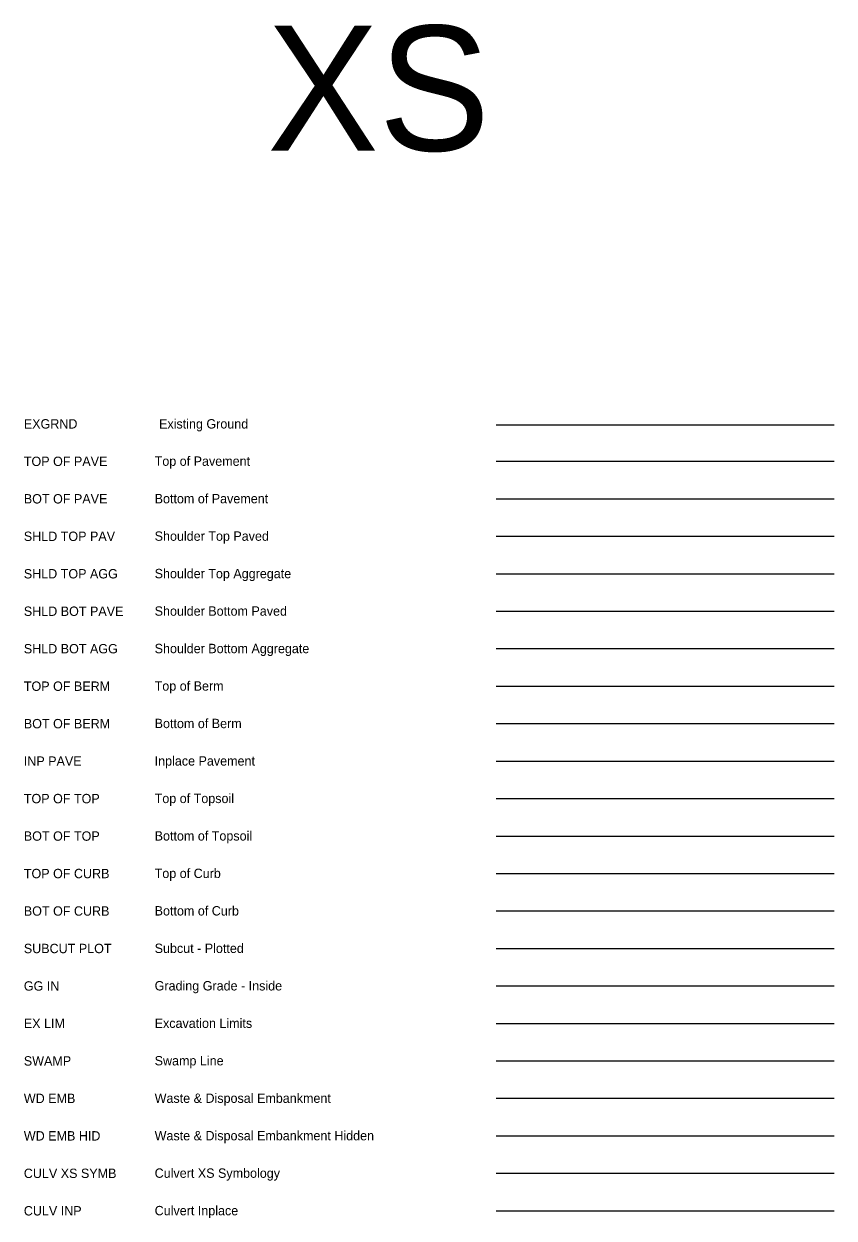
# Model space of a CAD drawing. Extents: x 2147716 to 2176321, y 2125040 to 2131750.
# Drawn here: x 2147716 to 2148364, y 2128683 to 2129640 of the extents above; entities that cross this region are included whole.
import ezdxf

# ---------------------------------------------------------------- set-up
doc = ezdxf.new("R2010")
doc.units = 0
for name, color, linetype in [('AGG HID', 7, 'Continuous'), ('BPFG CG BOT', 7, 'Continuous'), ('BPFG PAVE BOT', 7, 'Continuous'), ('BPFG SHLD BOT PAVE', 7, 'Continuous'), ('BPFG SWALK BOT', 7, 'Continuous'), ('CULV', 7, 'Continuous'), ('CULV INP', 7, 'Continuous'), ('DETAIL TXT', 7, 'Continuous'), ('EX LIM', 7, 'Continuous'), ('GRADE', 7, 'Continuous'), ('GRND INP', 7, 'Continuous'), ('PAVE INP', 7, 'Continuous'), ('PFG CG TOP', 7, 'Continuous'), ('PFG PAVE TOP', 7, 'Continuous'), ('PFG SHLD TOP', 7, 'Continuous'), ('PFG SWALK', 7, 'Continuous'), ('PFG TOPSOIL', 7, 'Continuous'), ('SUBCUT', 7, 'Continuous'), ('SWAMP EMBANK', 7, 'Continuous'), ('SWAMP EMBANK HID', 7, 'Continuous'), ('SWAMP LIN INP', 7, 'Continuous'), ('TOPSOIL BOT', 7, 'Continuous')]:
    doc.layers.add(name, color=color, linetype=linetype)

msp = doc.modelspace()

# ---------------------------------------------------------------- linework, layer by layer
at = {"layer": 'AGG HID'}
msp.add_line((2148094.06, 2129139.35), (2148364.47, 2129139.35), dxfattribs=at)
at = {"layer": 'BPFG CG BOT'}
msp.add_line((2148094.06, 2128929.35), (2148364.47, 2128929.35), dxfattribs=at)
at = {"layer": 'BPFG PAVE BOT'}
msp.add_line((2148094.06, 2129259.35), (2148364.47, 2129259.35), dxfattribs=at)
at = {"layer": 'BPFG SHLD BOT PAVE'}
msp.add_line((2148094.06, 2129169.35), (2148364.47, 2129169.35), dxfattribs=at)
at = {"layer": 'BPFG SWALK BOT'}
msp.add_line((2148094.06, 2129079.35), (2148364.47, 2129079.35), dxfattribs=at)
at = {"layer": 'CULV'}
msp.add_line((2148094.06, 2128719.35), (2148364.47, 2128719.35), dxfattribs=at)
at = {"layer": 'CULV INP'}
msp.add_line((2148094.06, 2128689.35), (2148364.47, 2128689.35), dxfattribs=at)
at = {"layer": 'EX LIM'}
msp.add_line((2148094.06, 2128839.35), (2148364.47, 2128839.35), dxfattribs=at)
at = {"layer": 'GRADE'}
msp.add_line((2148094.06, 2128869.35), (2148364.47, 2128869.35), dxfattribs=at)
at = {"layer": 'GRND INP'}
msp.add_line((2148094.06, 2129318.4), (2148364.47, 2129318.4), dxfattribs=at)
at = {"layer": 'PAVE INP'}
msp.add_line((2148094.06, 2129049.35), (2148364.47, 2129049.35), dxfattribs=at)
at = {"layer": 'PFG CG TOP'}
msp.add_line((2148094.06, 2128959.35), (2148364.47, 2128959.35), dxfattribs=at)
at = {"layer": 'PFG PAVE TOP'}
msp.add_line((2148094.06, 2129289.35), (2148364.47, 2129289.35), dxfattribs=at)
at = {"layer": 'PFG SHLD TOP'}
for p, q in [((2148094.06, 2129229.35), (2148364.47, 2129229.35)), ((2148094.06, 2129199.35), (2148364.47, 2129199.35))]:
    msp.add_line(p, q, dxfattribs=at)
at = {"layer": 'PFG SWALK'}
msp.add_line((2148094.06, 2129109.35), (2148364.47, 2129109.35), dxfattribs=at)
at = {"layer": 'PFG TOPSOIL'}
msp.add_line((2148094.06, 2129019.35), (2148364.47, 2129019.35), dxfattribs=at)
at = {"layer": 'SUBCUT'}
msp.add_line((2148094.06, 2128899.35), (2148364.47, 2128899.35), dxfattribs=at)
at = {"layer": 'SWAMP EMBANK'}
msp.add_line((2148094.06, 2128779.35), (2148364.47, 2128779.35), dxfattribs=at)
at = {"layer": 'SWAMP EMBANK HID'}
msp.add_line((2148094.06, 2128749.35), (2148364.47, 2128749.35), dxfattribs=at)
at = {"layer": 'SWAMP LIN INP'}
msp.add_line((2148094.06, 2128809.35), (2148364.47, 2128809.35), dxfattribs=at)
at = {"layer": 'TOPSOIL BOT'}
msp.add_line((2148094.06, 2128989.35), (2148364.47, 2128989.35), dxfattribs=at)

# ---------------------------------------------------------------- texts
at = {"layer": 'DETAIL TXT'}
for s, height, p in [('XS', 100, (2147910.73, 2129538.02)), ('EXGRND', 7.5, (2147715.95, 2129315.55)), ('Existing Ground', 7.5, (2147824.18, 2129315.55)), ('TOP OF PAVE', 7.5, (2147715.95, 2129285.55)), ('Top of Pavement', 7.5, (2147820.65, 2129285.7)), ('BOT OF PAVE', 7.5, (2147715.95, 2129255.55)), ('Bottom of Pavement', 7.5, (2147820.65, 2129255.7)), ('SHLD TOP PAV', 7.5, (2147715.95, 2129225.55)), ('Shoulder Top Paved', 7.5, (2147820.65, 2129225.7)), ('SHLD TOP AGG', 7.5, (2147715.95, 2129195.55)), ('Shoulder Top Aggregate', 7.5, (2147820.65, 2129195.7)), ('SHLD BOT PAVE', 7.5, (2147715.95, 2129165.55)), ('Shoulder Bottom Paved', 7.5, (2147820.65, 2129165.7)), ('SHLD BOT AGG', 7.5, (2147715.95, 2129135.55)), ('Shoulder Bottom Aggregate', 7.5, (2147820.65, 2129135.7)), ('TOP OF BERM', 7.5, (2147715.95, 2129105.55)), ('Top of Berm', 7.5, (2147820.65, 2129105.7)), ('BOT OF BERM', 7.5, (2147715.95, 2129075.55)), ('Bottom of Berm', 7.5, (2147820.65, 2129075.7)), ('INP PAVE', 7.5, (2147715.95, 2129045.55)), ('Inplace Pavement', 7.5, (2147820.65, 2129045.7)), ('TOP OF TOP', 7.5, (2147715.95, 2129015.55)), ('Top of Topsoil', 7.5, (2147820.65, 2129015.7)), ('BOT OF TOP', 7.5, (2147715.95, 2128985.55)), ('Bottom of Topsoil', 7.5, (2147820.65, 2128985.7)), ('TOP OF CURB', 7.5, (2147715.95, 2128955.55)), ('Top of Curb', 7.5, (2147820.65, 2128955.7)), ('BOT OF CURB', 7.5, (2147715.95, 2128925.55)), ('Bottom of Curb', 7.5, (2147820.65, 2128925.7)), ('SUBCUT PLOT', 7.5, (2147715.95, 2128895.55)), ('Subcut - Plotted', 7.5, (2147820.65, 2128895.7)), ('GG IN', 7.5, (2147715.95, 2128865.55)), ('Grading Grade - Inside', 7.5, (2147820.65, 2128865.7)), ('EX LIM', 7.5, (2147715.95, 2128835.55)), ('Excavation Limits', 7.5, (2147820.65, 2128835.7)), ('SWAMP', 7.5, (2147715.95, 2128805.55)), ('Swamp Line', 7.5, (2147820.65, 2128805.7)), ('Waste & Disposal Embankment', 7.5, (2147820.65, 2128775.7)), ('WD EMB', 7.5, (2147715.95, 2128775.55)), ('WD EMB HID', 7.5, (2147715.95, 2128745.55)), ('Waste & Disposal Embankment Hidden', 7.5, (2147820.65, 2128745.7)), ('CULV XS SYMB', 7.5, (2147715.95, 2128715.55)), ('Culvert XS Symbology', 7.5, (2147820.65, 2128715.7)), ('CULV INP', 7.5, (2147715.95, 2128685.55)), ('Culvert Inplace', 7.5, (2147820.65, 2128685.7))]:
    msp.add_text(s, height=height, dxfattribs=at).set_placement(p)

doc.saveas('drawing.dxf')
